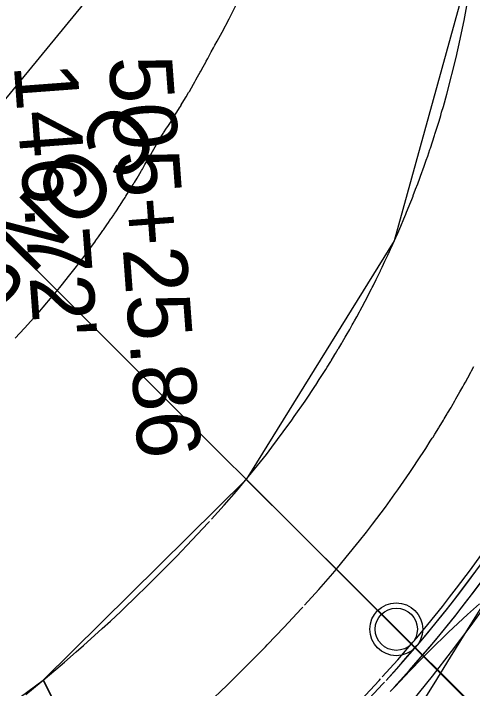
# Model space of a CAD drawing. Extents: x -70 to 701944, y -4 to 666871.
# Drawn here: x 664262.6 to 664306.1, y 656810.3 to 656874.1 of the extents above; entities that cross this region are included whole.
import ezdxf

# ---------------------------------------------------------------- set-up
doc = ezdxf.new("R2010")
doc.units = 0
for name, color, linetype in [('R_Detour', 7, 'Continuous'), ('R_Draft', 7, 'Continuous'), ('R_Horz Alg', 7, 'Continuous'), ('R_No Plot', 7, 'Continuous'), ('R_Proposed Const Limits', 7, 'Continuous'), ('R_Proposed Road', 7, 'Continuous'), ('R_ROW', 7, 'Continuous'), ('R_Striping', 7, 'Continuous'), ('R_Water', 7, 'Continuous'), ('T_Vehicle Path Lt Major', 7, 'Continuous'), ('T_Vehicle Path Rt', 7, 'Continuous')]:
    doc.layers.add(name, color=color, linetype=linetype)

msp = doc.modelspace()

# ---------------------------------------------------------------- linework, layer by layer
at = {"layer": 'R_Detour'}
msp.add_line((664241.347, 656873.241), (664326.935, 656787.909), dxfattribs=at)
at = {"layer": 'R_Draft'}
msp.add_arc((664209.617, 656892.347), 121, 317.35827, 2.48376, dxfattribs=at)
at = {"layer": 'R_Horz Alg'}
msp.add_arc((664209.617, 656892.347), 121, 317.35827, 2.48376, dxfattribs=at)
at = {"layer": 'R_No Plot'}
for points in [[(664379.541, 656735.865), (664372.11, 656835.588), (664368.394, 656885.45), (664306.432, 656880.833), (664298.662, 656852.633), (664284.644, 656830.074)], [(664265.435, 656811.102), (664284.644, 656830.074), (664379.542, 656735.865), (664305.746, 656730.366)], [(664249.778, 656799.571), (664265.405, 656811.081), (664305.74, 656730.449), (664255.216, 656726.6)]]:
    msp.add_lwpolyline(points, close=True, dxfattribs=at)
msp.add_lwpolyline([(664306.725, 656818.313), (664305.592, 656817.299), (664303.782, 656815.619), (664302.047, 656813.931), (664301.297, 656813.179), (664300.124, 656811.976), (664298.733, 656810.496), (664298.281, 656810.003)], dxfattribs=at)
msp.add_circle((664298.852, 656815.9), 2.5, dxfattribs=at)
at = {"layer": 'R_Proposed Const Limits'}
msp.add_lwpolyline([(664262.747, 656843.421), (664263.651, 656844.387), (664264.54, 656845.367), (664264.766, 656845.62), (664265.416, 656846.361), (664266.276, 656847.369), (664266.711, 656847.89), (664267.122, 656848.39), (664267.952, 656849.425), (664268.58, 656850.229), (664268.768, 656850.473), (664269.568, 656851.534), (664270.352, 656852.608), (664270.371, 656852.634), (664270.637, 656853.005), (664270.941, 656853.433), (664271.077, 656853.626), (664271.124, 656853.693), (664271.241, 656853.861), (664271.51, 656854.249), (664271.538, 656854.29), (664271.831, 656854.72), (664271.88, 656854.791), (664272.089, 656855.101), (664272.121, 656855.149), (664272.352, 656855.495), (664272.407, 656855.578), (664272.62, 656855.901), (664272.69, 656856.007), (664272.969, 656856.436), (664273.164, 656856.741), (664273.243, 656856.865), (664273.343, 656857.024), (664273.513, 656857.294), (664273.724, 656857.632), (664273.779, 656857.722), (664273.941, 656857.985), (664274.042, 656858.149), (664274.049, 656858.161), (664274.301, 656858.576), (664274.556, 656859.001), (664274.686, 656859.221), (664274.738, 656859.309), (664274.807, 656859.425), (664275.054, 656859.848), (664275.273, 656860.227), (664275.297, 656860.27), (664275.398, 656860.447), (664275.411, 656860.469), (664275.536, 656860.689), (664275.771, 656861.107), (664276.002, 656861.523), (664276.067, 656861.641), (664276.076, 656861.658), (664276.229, 656861.937), (664276.373, 656862.202), (664276.417, 656862.267), (664276.713, 656862.709), (664276.77, 656862.796), (664276.807, 656862.851), (664277.106, 656863.307), (664277.213, 656863.471), (664277.517, 656863.941), (664277.719, 656864.258), (664277.8, 656864.385), (664278.229, 656865.071), (664278.247, 656865.101), (664278.256, 656865.114), (664278.466, 656865.458), (664278.494, 656865.504), (664278.74, 656865.912), (664278.959, 656866.278), (664279.188, 656866.665), (664279.255, 656866.78), (664279.655, 656867.471), (664279.772, 656867.675), (664279.881, 656867.867), (664280.039, 656868.146), (664280.291, 656868.598), (664280.335, 656868.679), (664280.573, 656869.111), (664280.811, 656869.55), (664280.857, 656869.637), (664280.999, 656869.902), (664281.261, 656870.398), (664281.33, 656870.53), (664281.536, 656870.91), (664281.663, 656871.135), (664281.883, 656871.528), (664282.348, 656872.373), (664283.017, 656873.628), (664283.065, 656873.72), (664283.67, 656874.9)], dxfattribs=at)
at = {"layer": 'R_Proposed Road'}
for points in [[(664281.338, 656826.299), (664282.536, 656827.624), (664283.709, 656828.97), (664284.006, 656829.319), (664284.858, 656830.338), (664285.981, 656831.727), (664286.546, 656832.446), (664287.078, 656833.135), (664288.15, 656834.564), (664288.955, 656835.675), (664289.195, 656836.012), (664290.213, 656837.479), (664291.205, 656838.964), (664291.228, 656839.001), (664291.561, 656839.514), (664291.941, 656840.107), (664292.11, 656840.375), (664292.169, 656840.467), (664292.315, 656840.701), (664292.648, 656841.237), (664292.683, 656841.295), (664293.045, 656841.889), (664293.105, 656841.988), (664293.362, 656842.417), (664293.402, 656842.484), (664293.686, 656842.964), (664293.753, 656843.078), (664294.013, 656843.526), (664294.098, 656843.673), (664294.438, 656844.267), (664294.675, 656844.688), (664294.771, 656844.86), (664294.893, 656845.079), (664295.099, 656845.452), (664295.354, 656845.92), (664295.421, 656846.044), (664295.615, 656846.406), (664295.736, 656846.634), (664295.745, 656846.649), (664296.046, 656847.223), (664296.35, 656847.81), (664296.505, 656848.113), (664296.567, 656848.234), (664296.648, 656848.395), (664296.941, 656848.978), (664297.198, 656849.501), (664297.227, 656849.559), (664297.345, 656849.803), (664297.36, 656849.834), (664297.507, 656850.138), (664297.781, 656850.714), (664298.049, 656851.287), (664298.124, 656851.448), (664298.135, 656851.472), (664298.312, 656851.856), (664298.477, 656852.221), (664298.52, 656852.314), (664298.804, 656852.951), (664298.859, 656853.076), (664298.894, 656853.156), (664299.178, 656853.81), (664299.279, 656854.045), (664299.563, 656854.717), (664299.751, 656855.17), (664299.826, 656855.353), (664300.22, 656856.328), (664300.237, 656856.371), (664300.245, 656856.39), (664300.436, 656856.877), (664300.462, 656856.943), (664300.685, 656857.52), (664300.881, 656858.037), (664301.084, 656858.582), (664301.143, 656858.744), (664301.494, 656859.714), (664301.595, 656860.001), (664301.689, 656860.269), (664301.824, 656860.659), (664302.039, 656861.291), (664302.076, 656861.402), (664302.275, 656862.004), (664302.473, 656862.613), (664302.511, 656862.734), (664302.627, 656863.101), (664302.84, 656863.787), (664302.896, 656863.969), (664303.054, 656864.495), (664303.147, 656864.809), (664303.307, 656865.357), (664303.636, 656866.527), (664304.093, 656868.253), (664304.125, 656868.379), (664304.519, 656869.987), (664304.912, 656871.729), (664305.035, 656872.304), (664305.274, 656873.478), (664305.603, 656875.233)], [(664290.166, 656818.171), (664291.511, 656819.658), (664292.828, 656821.17), (664293.161, 656821.561), (664294.118, 656822.706), (664295.379, 656824.266), (664296.014, 656825.073), (664296.612, 656825.848), (664297.815, 656827.452), (664298.72, 656828.7), (664298.989, 656829.078), (664300.133, 656830.726), (664301.246, 656832.394), (664301.273, 656832.435), (664301.647, 656833.011), (664302.073, 656833.677), (664302.263, 656833.978), (664302.329, 656834.082), (664302.493, 656834.344), (664302.867, 656834.947), (664302.906, 656835.011), (664303.313, 656835.679), (664303.38, 656835.79), (664303.67, 656836.272), (664303.714, 656836.347), (664304.033, 656836.886), (664304.108, 656837.015), (664304.4, 656837.517), (664304.496, 656837.682), (664304.877, 656838.349), (664305.144, 656838.822), (664305.252, 656839.015), (664305.389, 656839.262), (664305.62, 656839.68), (664305.906, 656840.205), (664305.981, 656840.345), (664306.2, 656840.752)], [(664263.758, 656809.727), (664265.207, 656810.916), (664265.604, 656811.246), (664267.426, 656812.793), (664268.53, 656813.751), (664269.226, 656814.366), (664271.003, 656815.965), (664271.775, 656816.675), (664272.756, 656817.591), (664274.484, 656819.242), (664274.94, 656819.686), (664276.189, 656820.918), (664277.868, 656822.62), (664278.024, 656822.78), (664279.522, 656824.345), (664281.023, 656825.956), (664281.147, 656826.091), (664281.151, 656826.095)], [(664297.522, 656811.396), (664298.99, 656813.02), (664300.428, 656814.67), (664300.791, 656815.097), (664301.835, 656816.346), (664303.211, 656818.048), (664303.904, 656818.929), (664304.557, 656819.775), (664305.87, 656821.526), (664306.857, 656822.887)], [(664297.882, 656811.064), (664299.356, 656812.695), (664300.8, 656814.352), (664301.165, 656814.78), (664302.213, 656816.035), (664303.595, 656817.743), (664304.291, 656818.628), (664304.946, 656819.477), (664306.264, 656821.235)], [(664298.625, 656810.38), (664300.111, 656812.024), (664301.567, 656813.695), (664301.935, 656814.127), (664302.992, 656815.392), (664304.386, 656817.115), (664305.088, 656818.008), (664305.748, 656818.864), (664307.078, 656820.637)], [(664280.98, 656808.852), (664282.836, 656810.625), (664283.326, 656811.102), (664284.666, 656812.425), (664286.47, 656814.252), (664286.637, 656814.424), (664288.246, 656816.105), (664289.857, 656817.835), (664289.99, 656817.98), (664289.995, 656817.985)], [(664295.516, 656809.239), (664297.219, 656811.067), (664297.36, 656811.221), (664297.365, 656811.226)], [(664295.872, 656808.903), (664297.58, 656810.736), (664297.721, 656810.89), (664297.726, 656810.895)]]:
    msp.add_lwpolyline(points, dxfattribs=at)
msp.add_arc((664209.617, 656892.347), 120, 317.35827, 2.48376, dxfattribs=at)
at = {"layer": 'R_ROW'}
msp.add_lwpolyline([(664304.964, 657008.589), (664269.223, 656875.051), (664229.686, 656826.98), (664172.914, 656800.844), (664112.646, 656789.663), (663906.505, 656801.428), (663861.109, 656796.118)], dxfattribs=at)
at = {"layer": 'R_Striping'}
for centre, radius, start, end in [((664379.542, 656735.865), 90, 2.50537, 328.76296), ((664517.938, 656349.929), 500, 109.73256, 120.87769)]:
    msp.add_arc(centre, radius, start, end, dxfattribs=at)
at = {"layer": 'R_Water'}
msp.add_circle((664298.852, 656815.9), 2, dxfattribs=at)
at = {"layer": 'T_Vehicle Path Lt Major'}
msp.add_lwpolyline([(664307.083, 656818.271), (664305.505, 656815.755), (664303.943, 656813.248), (664302.39, 656810.753), (664300.844, 656808.283)], dxfattribs=at)
msp.add_arc((664379.542, 656735.865), 90, 2.50537, 328.76296, dxfattribs=at)
at = {"layer": 'T_Vehicle Path Rt'}
msp.add_lwpolyline([(664319.183, 656837.663), (664318.351, 656836.061), (664316.929, 656833.425), (664315.465, 656830.833), (664313.96, 656828.286), (664312.416, 656825.784), (664310.834, 656823.326), (664309.217, 656820.911), (664307.556, 656818.528), (664305.828, 656816.142), (664304.056, 656813.79), (664302.236, 656811.464), (664300.374, 656809.172), (664298.421, 656806.859), (664296.375, 656804.528), (664294.282, 656802.236), (664293.003, 656800.879)], dxfattribs=at)

# ---------------------------------------------------------------- texts
at = {"layer": 'R_No Plot'}
for s, p in [('505+25.86 ', (664271.598, 656869.946)), ("146.72' ", (664262.623, 656869.277))]:
    msp.add_text(s, height=6, rotation=274.26194, dxfattribs=at).set_placement(p)
at = {"layer": 'R_Proposed Const Limits'}
msp.add_text('CONST. LIMITS', height=6, rotation=225.40156, dxfattribs=at).set_placement((664272.535, 656866.258))

doc.saveas('drawing.dxf')
